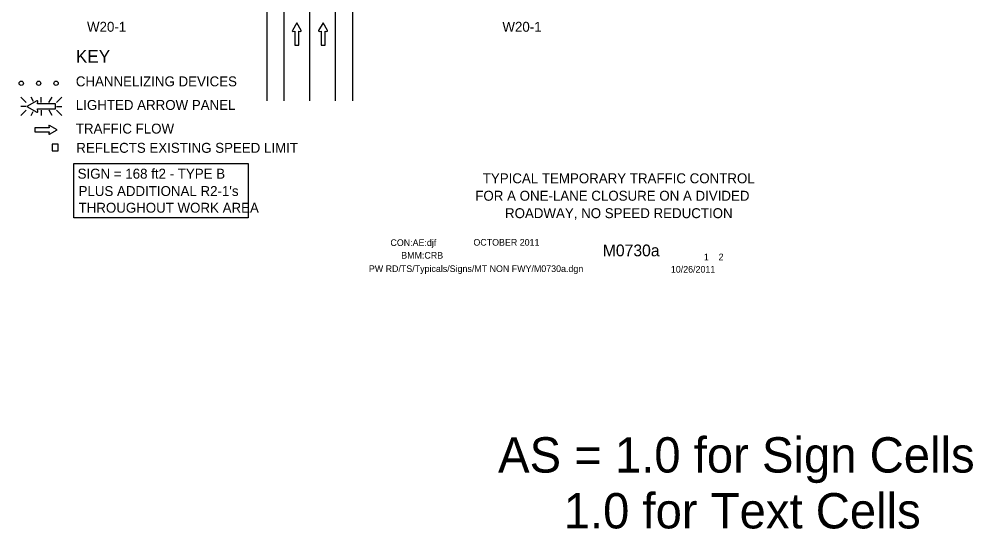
# Model space of a CAD drawing. Extents: x 16738 to 18475, y 6980 to 8209.
# Drawn here: x 16743 to 17635, y 6980 to 7456 of the extents above; entities that cross this region are included whole.
import ezdxf

# ---------------------------------------------------------------- set-up
doc = ezdxf.new("R2010")
doc.units = 0
for name, color, linetype in [('ALI_LEGAL_EX', 7, 'Continuous'), ('BORDER', 7, 'Continuous'), ('BORDER_SIGNAL_WO', 7, 'Continuous'), ('MT_SCRATCH_LEVEL_E', 7, 'Continuous'), ('PAVT_EDGE_EX', 7, 'Continuous'), ('TRAFFIC_SIGNS_PR', 7, 'Continuous'), ('TYPICAL_TEXT_DIMEN_EX', 7, 'Continuous')]:
    doc.layers.add(name, color=color, linetype=linetype)

msp = doc.modelspace()

# ---------------------------------------------------------------- linework, layer by layer
at = {"layer": 'ALI_LEGAL_EX'}
msp.add_lwpolyline([(17015.15, 7409.25), (17015.15, 7384.25)], dxfattribs=at)
at = {"layer": 'MT_SCRATCH_LEVEL_E'}
for p, q in [((17003.12, 7452.89), (16999.01, 7445.65)), ((17003.12, 7452.89), (16999.01, 7445.65)), ((17007.27, 7445.65), (17003.12, 7452.89)), ((17007.27, 7445.65), (17003.12, 7452.89)), ((17027.68, 7452.89), (17023.57, 7445.65)), ((17027.68, 7452.89), (17023.57, 7445.65)), ((17031.83, 7445.65), (17027.68, 7452.89)), ((17031.83, 7445.65), (17027.68, 7452.89)), ((16999.49, 7444.96), (17001.27, 7445.28)), ((16999.49, 7444.96), (17001.27, 7445.28)), ((17001.27, 7445.28), (17001.27, 7432.02)), ((17001.27, 7445.28), (17001.27, 7432.02)), ((17005.01, 7432.02), (17005.01, 7445.28)), ((17005.01, 7445.28), (17006.79, 7444.96)), ((17005.01, 7432.02), (17005.01, 7445.28)), ((17005.01, 7445.28), (17006.79, 7444.96)), ((17024.05, 7444.96), (17025.83, 7445.28)), ((17024.05, 7444.96), (17025.83, 7445.28)), ((17025.83, 7445.28), (17025.83, 7432.02)), ((17025.83, 7445.28), (17025.83, 7432.02)), ((17029.57, 7432.02), (17029.57, 7445.28)), ((17029.57, 7445.28), (17031.35, 7444.96)), ((17029.57, 7432.02), (17029.57, 7445.28)), ((17029.57, 7445.28), (17031.35, 7444.96)), ((17001.27, 7432.02), (17005.01, 7432.02)), ((17001.27, 7432.02), (17005.01, 7432.02)), ((17025.83, 7432.02), (17029.57, 7432.02)), ((17025.83, 7432.02), (17029.57, 7432.02)), ((16771.47, 7354.82), (16758.21, 7354.82)), ((16758.21, 7354.82), (16758.21, 7351.08)), ((16771.47, 7354.82), (16758.21, 7354.82)), ((16758.21, 7354.82), (16758.21, 7351.08)), ((16758.21, 7351.08), (16771.47, 7351.08)), ((16758.21, 7351.08), (16771.47, 7351.08)), ((16771.15, 7356.6), (16771.47, 7354.82)), ((16771.15, 7356.6), (16771.47, 7354.82)), ((16771.47, 7351.08), (16771.15, 7349.3)), ((16771.47, 7351.08), (16771.15, 7349.3)), ((16779.08, 7352.97), (16771.84, 7357.08)), ((16779.08, 7352.97), (16771.84, 7357.08)), ((16771.84, 7348.82), (16779.08, 7352.97)), ((16771.84, 7348.82), (16779.08, 7352.97))]:
    msp.add_line(p, q, dxfattribs=at)
for centre, start, end in [((16999.42, 7445.42), 150.42484, 279.96381), ((16999.42, 7445.42), 150.42484, 279.96381), ((17006.86, 7445.42), 260.03619, 29.77312), ((17006.86, 7445.42), 260.03619, 29.77312), ((17023.98, 7445.42), 150.42484, 279.96381), ((17023.98, 7445.42), 150.42484, 279.96381), ((17031.42, 7445.42), 260.03619, 29.77312), ((17031.42, 7445.42), 260.03619, 29.77312), ((16771.61, 7356.67), 60.42484, 189.96381), ((16771.61, 7356.67), 60.42484, 189.96381), ((16771.61, 7349.23), 170.03619, 299.77312), ((16771.61, 7349.23), 170.03619, 299.77312)]:
    msp.add_arc(centre, 0.463, start, end, dxfattribs=at)
at = {"layer": 'PAVT_EDGE_EX'}
for p, q in [((16975.15, 8209.25), (16975.15, 7380.06)), ((16991.15, 8209.25), (16991.15, 7380.06)), ((17015.15, 8209.25), (17015.15, 7380.06)), ((17039.15, 8209.25), (17039.15, 7380.06)), ((17055.15, 8209.25), (17055.15, 7380.06))]:
    msp.add_line(p, q, dxfattribs=at)
at = {"layer": 'TRAFFIC_SIGNS_PR'}
for p, q in [((16745.11, 7383.29), (16750.04, 7378.36)), ((16756.87, 7379.47), (16754.66, 7383.29)), ((16764.19, 7378.36), (16764.19, 7383.29)), ((16771.43, 7378.36), (16774.28, 7383.29)), ((16778.34, 7378.36), (16783.28, 7383.29)), ((16750.04, 7374.8), (16745.11, 7374.8)), ((16745.11, 7366.31), (16750.04, 7371.25)), ((16754.62, 7366.31), (16756.73, 7369.97)), ((16764.19, 7371.25), (16764.19, 7366.31)), ((16774.32, 7366.31), (16771.47, 7371.25)), ((16778.34, 7374.8), (16783.28, 7374.8)), ((16778.34, 7371.25), (16783.28, 7366.31))]:
    msp.add_line(p, q, dxfattribs=at)
for points in [[(16760.12, 7380.08), (16750.83, 7374.8), (16760.12, 7369.48)], [(16760.99, 7370.11), (16760.59, 7372.38), (16777.61, 7372.38), (16777.61, 7377.18), (16760.59, 7377.18), (16761, 7379.46)]]:
    msp.add_lwpolyline(points, dxfattribs=at)
msp.add_lwpolyline([(16774.41, 7333.24), (16780, 7333.24), (16780, 7339.41), (16774.41, 7339.41)], close=True, dxfattribs=at)
for centre in [(16745.45, 7396.49), (16761.75, 7396.49), (16778.05, 7396.49)]:
    msp.add_circle(centre, 2, dxfattribs=at)
for centre, radius, start, end in [((16760.41, 7379.55), 0.598, 350.73078, 118.89165), ((16760.41, 7370), 0.597, 241.48329, 9.95933)]:
    msp.add_arc(centre, radius, start, end, dxfattribs=at)
at = {"layer": 'TYPICAL_TEXT_DIMEN_EX'}
msp.add_lwpolyline([(16794.76, 7321.26), (16957.51, 7321.26), (16957.51, 7270.6), (16794.76, 7270.6)], close=True, dxfattribs=at)

# ---------------------------------------------------------------- texts
at = {"layer": 'BORDER'}
for s, p in [('TYPICAL TEMPORARY TRAFFIC CONTROL', (17177.02, 7302.9)), ('FOR A ONE-LANE CLOSURE ON A DIVIDED', (17170.05, 7286.6)), ('ROADWAY, NO SPEED REDUCTION', (17197.83, 7270.3))]:
    msp.add_text(s, height=9.3, dxfattribs=at).set_placement(p)
at = {"layer": 'BORDER_SIGNAL_WO'}
for s, height, p in [('CON:AE:djf', 6.2, (17090.69, 7244.31)), ('    OCTOBER 2011    ', 6.2, (17159.08, 7244.59)), ('    M0730a   ', 11, (17272.86, 7234.63)), ('BMM:CRB   ', 6.2, (17100.81, 7232.42)), (' 1    2 ', 6.2, (17381.45, 7230.95)), ('PW RD/TS/Typicals/Signs/MT NON FWY/M0730a.dgn    ', 6.2, (17070.55, 7219.96)), ('10/26/2011    ', 6.2, (17352.93, 7219.38)), ('AS = 1.0 for Sign Cells', 33.0301, (17191.35, 7032.43)), ('     1.0 for Text Cells', 33.0301, (17191.35, 6980.2))]:
    msp.add_text(s, height=height, dxfattribs=at).set_placement(p)
at = {"layer": 'TRAFFIC_SIGNS_PR'}
for p in [(16806.98, 7444.58), (17195.4, 7444.56)]:
    msp.add_text('W20-1', height=9.3, dxfattribs=at).set_placement(p)
at = {"layer": 'TYPICAL_TEXT_DIMEN_EX'}
for s, height, p in [('KEY', 12, (16796.52, 7415.59)), ('CHANNELIZING DEVICES', 9.3, (16796.52, 7393.54)), ('LIGHTED ARROW PANEL', 9.3, (16796.52, 7371.49)), ('TRAFFIC FLOW', 9.3, (16796.52, 7349.38)), ('REFLECTS EXISTING SPEED LIMIT', 9.3, (16796.93, 7331.4)), ('SIGN = 168 ft2 - TYPE B', 9.3, (16798.2, 7307.22)), ("PLUS ADDITIONAL R2-1's", 9.3, (16799.08, 7291)), ('THROUGHOUT WORK AREA', 9.3, (16799.08, 7275.4))]:
    msp.add_text(s, height=height, dxfattribs=at).set_placement(p)

doc.saveas('drawing.dxf')
